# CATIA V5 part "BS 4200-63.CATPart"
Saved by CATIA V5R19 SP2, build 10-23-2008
Part number: BS 4200-63
Bounding box of the stored display mesh (mm): x -47.487 to 47.487, y -47.487 to 47.487, z 0 to 191
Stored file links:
  C:\Users\Bora\Desktop\3D Katı model\BS serisi\BS 4200\BS 4200-63.CATPart
  C:\Program Files\Dassault Systemes\B19\intel_a\reffiles\standard\MetricThickPitch.txt
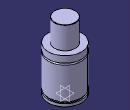
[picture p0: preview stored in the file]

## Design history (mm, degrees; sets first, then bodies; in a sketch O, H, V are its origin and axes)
Body1 (main body)
  Sketch1 on yz-plane, origin (0, 0, 0), H (0, 1, 0), V (0, 0, 1)
    point P2 (47.5, 103.5)
    point P5 (30, 190)
    point P7 (30, 190)
    point P11 (47.5, 108.5)
    point P13 (47.5, 108.5)
    point P14 (47.5, 103.5)
    line L1 (47.5, 13) -> (47.5, 103.5)
    line L2 (44.5, 13) -> (44.5, 8)
    line L3 (30, 190) -> (30, 127)
    arc A1 centre (29, 190) radius 1 from (30, 190) to (29, 191) ccw
    line L4 (47.5, 0) -> (47.5, 8)
    line L5 (47.5, 108.5) -> (47.5, 127)
    arc A2 centre (47.5, 106) radius 2.5 from (47.5, 108.5) to (47.5, 103.5) ccw
    line L6 (29, 191) -> (0, 191)
    point P15 (0, 191)
    line L7 (30, 127) -> (47.5, 127)
    line L8 (44.5, 13) -> (47.5, 13)
    line L9 (44.5, 8) -> (47.5, 8)
    line L10 (0, 0) -> (47.5, 0)
    tangency: L6 A1
    coincidence: P15 V, P2 P14, P5 P7, P11 P13
    horizontal: L7 H, L8 H, L9 H, L10 H
  Shaft1: profile Sketch1, axis Sketch1.V, angle 360
  Sketch2 on face of Shaft1 from Sketch1.L10, origin (0, 0, 0), H (1, 0, 0), V (0, -1, 0)
    point P1 (30, 0)
    distance P1 V = 30
  Hole1: placed by Sketch2, at (30, 0, 0) direction (0, 0, 1), diameter 6.647, depth 7, threaded "M8", thread diameter 8, thread depth 7, pitch 1.25
  CircPattern1: of Hole1, instances 4, angular step 90, axis from xy-plane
